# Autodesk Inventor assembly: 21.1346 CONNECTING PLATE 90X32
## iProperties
Created: 2007-01
Part Number: 21.1346 CONNECTING PLATE 90X32
Document SubType Name: Assembly
Designer: Andy Moles
Author: Andy Moles
